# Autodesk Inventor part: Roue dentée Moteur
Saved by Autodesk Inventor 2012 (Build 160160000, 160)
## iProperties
Created: 2013-08
Part Number: Roue dentée Moteur
Material: Default
Document SubType Name: Modeling
Designer: hilarion
Density: 1 g/cm^3
Author: Balduini Gael & Faure Olivier
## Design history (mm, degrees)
node "Roue dentée Moteur1"
node "Roue dentée Moteur"
node "Base1"
